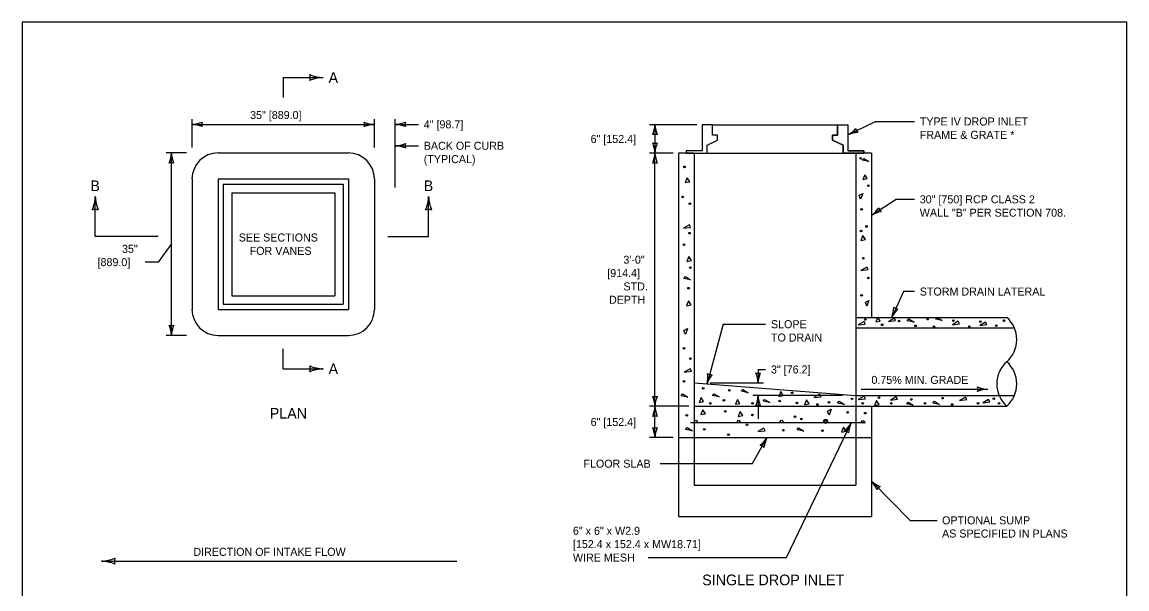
# Model space of a CAD drawing. Extents: x 49991.4 to 50021, y 49987.6 to 50011.4.
# Drawn here: x 50000.34 to 50008.61, y 50007.02 to 50011.26 of the extents above; entities that cross this region are included whole.
import ezdxf

# ---------------------------------------------------------------- set-up
doc = ezdxf.new("R2010")
doc.units = 0
for name, color, linetype in [('Level 1', 7, 'Continuous'), ('Level 2', 7, 'Continuous'), ('Level 3', 7, 'Continuous'), ('Level 4', 7, 'Continuous'), ('Level 6', 7, 'Continuous')]:
    doc.layers.add(name, color=color, linetype=linetype)

msp = doc.modelspace()

# ---------------------------------------------------------------- linework, layer by layer
at = {"layer": 'Level 1'}
for p, q in [((50005.5095, 50010.4937), (50005.4325, 50010.4937)), ((50005.4325, 50010.4937), (50005.4325, 50010.2985)), ((50005.5095, 50010.4937), (50005.4325, 50010.4937)), ((50005.4325, 50010.4937), (50005.4325, 50010.2985)), ((50005.5095, 50010.4169), (50005.5095, 50010.4937)), ((50005.5095, 50010.4169), (50005.5095, 50010.4937)), ((50005.5095, 50010.4937), (50006.4458, 50010.4937)), ((50006.4458, 50010.4169), (50006.4458, 50010.4937)), ((50006.4458, 50010.4937), (50006.5227, 50010.4937)), ((50006.4458, 50010.4937), (50006.4458, 50010.4169)), ((50006.4458, 50010.4937), (50006.5227, 50010.4937)), ((50006.5227, 50010.4937), (50006.5227, 50010.2985)), ((50006.5227, 50010.4937), (50006.5227, 50010.2985)), ((50006.5227, 50010.4937), (50006.5227, 50010.2985)), ((50005.4681, 50010.3404), (50005.5461, 50010.3795)), ((50005.4681, 50010.3404), (50005.5461, 50010.3795)), ((50005.5461, 50010.4169), (50005.5095, 50010.4169)), ((50005.5461, 50010.4169), (50005.5095, 50010.4169)), ((50005.5461, 50010.3795), (50005.5461, 50010.4169)), ((50005.5461, 50010.3795), (50005.5461, 50010.4169)), ((50006.4091, 50010.3795), (50006.4091, 50010.4169)), ((50006.4091, 50010.4169), (50006.4458, 50010.4169)), ((50006.4458, 50010.4169), (50006.4091, 50010.4169)), ((50006.4091, 50010.4169), (50006.4091, 50010.3795)), ((50006.4873, 50010.3404), (50006.4091, 50010.3795)), ((50006.4091, 50010.3795), (50006.4873, 50010.3404)), ((50005.4325, 50010.2985), (50005.3119, 50010.2985)), ((50005.3119, 50010.2985), (50005.3119, 50010.2811)), ((50005.4325, 50010.2985), (50005.3119, 50010.2985)), ((50005.3119, 50010.2985), (50005.3119, 50010.2811)), ((50005.4681, 50010.2811), (50005.4681, 50010.3404)), ((50005.4681, 50010.2811), (50005.4681, 50010.3404)), ((50006.4873, 50010.2811), (50006.4873, 50010.3404)), ((50006.4873, 50010.3404), (50006.4873, 50010.2811)), ((50006.5227, 50010.2985), (50006.6435, 50010.2985)), ((50006.6435, 50010.2985), (50006.5227, 50010.2985)), ((50006.6435, 50010.2985), (50006.6435, 50010.2811)), ((50006.6435, 50010.2811), (50006.6435, 50010.2985)), ((50001.804, 50010.2826), (50002.7806, 50010.2826)), ((50002.7806, 50010.2826), (50002.7806, 50010.2827)), ((50005.3721, 50010.2811), (50005.2551, 50010.2811)), ((50005.2551, 50010.2811), (50005.2551, 50008.1497)), ((50005.3119, 50010.2811), (50005.4681, 50010.2811)), ((50005.3119, 50010.2811), (50005.4681, 50010.2811)), ((50005.3721, 50010.2811), (50005.3721, 50008.3843)), ((50005.4681, 50010.2811), (50006.4873, 50010.2811)), ((50006.6435, 50010.2811), (50006.4873, 50010.2811)), ((50006.4873, 50010.2811), (50006.6435, 50010.2811)), ((50006.7003, 50010.2811), (50006.5831, 50010.2811)), ((50006.5831, 50010.2811), (50006.5831, 50008.3864)), ((50006.7003, 50010.2811), (50006.7003, 50009.0505)), ((50001.6087, 50010.0874), (50001.6087, 50010.0874)), ((50001.6088, 50010.0874), (50001.6088, 50009.1108)), ((50001.804, 50010.0874), (50001.804, 50009.1108)), ((50001.804, 50010.0874), (50002.7806, 50010.0874)), ((50001.843, 50010.0482), (50001.843, 50009.1498)), ((50001.843, 50010.0482), (50002.7416, 50010.0482)), ((50002.7416, 50010.0482), (50002.7416, 50009.1498)), ((50002.7806, 50010.0874), (50002.7806, 50009.1108)), ((50002.9758, 50010.0874), (50002.9758, 50009.1108)), ((50001.9066, 50009.9848), (50001.9066, 50009.2133)), ((50001.9066, 50009.9848), (50002.678, 50009.9848)), ((50002.678, 50009.9848), (50002.678, 50009.2133)), ((50001.843, 50009.1498), (50002.7416, 50009.1498)), ((50001.9066, 50009.2133), (50002.678, 50009.2133)), ((50001.6087, 50009.1108), (50001.6088, 50009.1108)), ((50001.804, 50009.1108), (50002.7806, 50009.1108)), ((50002.9758, 50009.1108), (50002.9759, 50009.1108)), ((50006.5831, 50009.0505), (50007.7142, 50009.0505)), ((50006.5831, 50008.9723), (50007.771, 50008.9723)), ((50001.804, 50008.9155), (50001.804, 50008.9154)), ((50001.804, 50008.9154), (50002.7806, 50008.9154)), ((50005.3721, 50008.5598), (50006.5831, 50008.4646)), ((50006.5831, 50008.4646), (50007.771, 50008.4646)), ((50005.3721, 50008.3843), (50006.5831, 50008.3864)), ((50006.5831, 50008.3864), (50007.7143, 50008.3864)), ((50006.7003, 50008.3864), (50006.7003, 50008.1497)), ((50006.6563, 50008.2606), (50005.3449, 50008.2606)), ((50005.2551, 50008.1497), (50006.7003, 50008.1497))]:
    msp.add_line(p, q, dxfattribs=at)
for points in [[(50008.6146, 50011.2628), (50000.3356, 50011.2628), (50000.3356, 50000.0624), (50008.6146, 50000.0624)], [(50001.6087, 50010.0874), (50001.6087, 50010.0874), (50001.6087, 50010.0874)], [(50001.804, 50008.9155), (50001.804, 50008.9155), (50001.804, 50008.9155)], [(50001.804, 50008.9154), (50001.804, 50008.9154), (50001.804, 50008.9154)], [(50001.804, 50008.9154), (50001.804, 50008.9154), (50001.804, 50008.9154)], [(50002.7806, 50008.9155), (50002.7806, 50008.9155)]]:
    msp.add_lwpolyline(points, close=True, dxfattribs=at)
for points in [[(50006.6427, 50010.2417), (50006.6819, 50010.2177), (50006.6313, 50010.2277), (50006.6427, 50010.2417)], [(50001.6088, 50010.0874), (50001.6088, 50010.0874), (50001.6087, 50010.0874)], [(50005.3197, 50010.0962), (50005.3045, 50010.06), (50005.3383, 50010.0667), (50005.3197, 50010.0962)], [(50006.6499, 50010.1197), (50006.6347, 50010.0835), (50006.6685, 50010.0902), (50006.6499, 50010.1197)], [(50006.6189, 50009.9355), (50006.6077, 50009.9661), (50006.6347, 50009.9795), (50006.6189, 50009.9355)], [(50005.3357, 50009.7431), (50005.2911, 50009.7178), (50005.3449, 50009.7245), (50005.3357, 50009.7431)], [(50006.6365, 50009.6634), (50006.6213, 50009.6272), (50006.6549, 50009.6339), (50006.6365, 50009.6634)], [(50005.3331, 50009.5057), (50005.3181, 50009.4695), (50005.3517, 50009.4762), (50005.3331, 50009.5057)], [(50006.6657, 50009.4277), (50006.6213, 50009.4024), (50006.6751, 50009.4091), (50006.6657, 50009.4277)], [(50005.3057, 50009.356), (50005.3449, 50009.3319), (50005.2945, 50009.342), (50005.3057, 50009.356)], [(50005.3299, 50009.1736), (50005.3147, 50009.1373), (50005.3483, 50009.1441), (50005.3299, 50009.1736)], [(50006.6661, 50009.1336), (50006.6549, 50009.1642), (50006.6819, 50009.1776), (50006.6661, 50009.1336)], [(50006.7479, 50009.0524), (50006.7329, 50009.0162), (50006.7665, 50009.0229), (50006.7479, 50009.0524)], [(50006.6446, 50009.0196), (50006.6002, 50008.9943), (50006.654, 50009.001), (50006.6446, 50009.0196)], [(50006.8721, 50009.045), (50006.8277, 50009.0197), (50006.8815, 50009.0264), (50006.8721, 50009.045)], [(50006.9801, 50009.0389), (50007.0193, 50009.0148), (50006.9689, 50009.0249), (50006.9801, 50009.0389)], [(50007.1922, 50009.0503), (50007.2314, 50009.0262), (50007.181, 50009.0363), (50007.1922, 50009.0503)], [(50007.351, 50009.0212), (50007.3066, 50008.9959), (50007.3604, 50009.0026), (50007.351, 50009.0212)], [(50007.5561, 50009.0149), (50007.5117, 50008.9896), (50007.5655, 50008.9963), (50007.5561, 50009.0149)], [(50005.3057, 50008.9223), (50005.2945, 50008.9528), (50005.3215, 50008.9663), (50005.3057, 50008.9223)], [(50005.3423, 50008.6661), (50005.2979, 50008.6408), (50005.3517, 50008.6475), (50005.3423, 50008.6661)], [(50005.2855, 50008.477), (50005.3247, 50008.4529), (50005.2743, 50008.463), (50005.2855, 50008.477)], [(50005.5189, 50008.479), (50005.5581, 50008.4549), (50005.5077, 50008.465), (50005.5189, 50008.479)], [(50005.7368, 50008.5107), (50005.776, 50008.4866), (50005.7256, 50008.4967), (50005.7368, 50008.5107)], [(50006.0208, 50008.4953), (50006.0056, 50008.459), (50006.0392, 50008.4657), (50006.0208, 50008.4953)], [(50006.3131, 50008.4751), (50006.2685, 50008.4498), (50006.3223, 50008.4565), (50006.3131, 50008.4751)], [(50005.4232, 50008.4497), (50005.4082, 50008.4135), (50005.4418, 50008.4202), (50005.4232, 50008.4497)], [(50005.6956, 50008.4355), (50005.6806, 50008.3993), (50005.7142, 50008.406), (50005.6956, 50008.4355)], [(50005.8991, 50008.4362), (50005.9383, 50008.4121), (50005.8879, 50008.4222), (50005.8991, 50008.4362)], [(50006.2146, 50008.4326), (50006.1996, 50008.3964), (50006.2332, 50008.4031), (50006.2146, 50008.4326)], [(50006.4582, 50008.422), (50006.4974, 50008.3979), (50006.447, 50008.408), (50006.4582, 50008.422)], [(50006.6462, 50008.4602), (50006.6018, 50008.4349), (50006.6556, 50008.4416), (50006.6462, 50008.4602)], [(50006.7393, 50008.4269), (50006.7243, 50008.3907), (50006.7579, 50008.3974), (50006.7393, 50008.4269)], [(50006.8864, 50008.4555), (50006.842, 50008.4302), (50006.8958, 50008.4369), (50006.8864, 50008.4555)], [(50006.9743, 50008.4162), (50007.0135, 50008.3921), (50006.9631, 50008.4022), (50006.9743, 50008.4162)], [(50007.1722, 50008.422), (50007.2114, 50008.3979), (50007.161, 50008.408), (50007.1722, 50008.422)], [(50007.4051, 50008.4539), (50007.3607, 50008.4286), (50007.4145, 50008.4353), (50007.4051, 50008.4539)], [(50007.5785, 50008.4364), (50007.5341, 50008.4111), (50007.5879, 50008.4178), (50007.5785, 50008.4364)], [(50005.4375, 50008.3583), (50005.4225, 50008.3221), (50005.4561, 50008.3288), (50005.4375, 50008.3583)], [(50005.7171, 50008.3449), (50005.7019, 50008.3087), (50005.7357, 50008.3153), (50005.7171, 50008.3449)], [(50006.3833, 50008.3183), (50006.3721, 50008.3489), (50006.3991, 50008.3623), (50006.3833, 50008.3183)], [(50005.3191, 50008.2253), (50005.3585, 50008.2013), (50005.3079, 50008.2113), (50005.3191, 50008.2253)], [(50006.4917, 50008.2275), (50006.4765, 50008.1912), (50006.5101, 50008.1979), (50006.4917, 50008.2275)], [(50005.8947, 50008.2199), (50005.8501, 50008.1946), (50005.9039, 50008.2013), (50005.8947, 50008.2199)], [(50006.1543, 50008.222), (50006.1935, 50008.1979), (50006.1431, 50008.208), (50006.1543, 50008.222)]]:
    msp.add_lwpolyline(points, dxfattribs=at)
for centre, radius in [((50006.6196, 50010.242), 0.00606), ((50005.2995, 50010.1783), 0.00606), ((50006.6768, 50010.0373), 0.00606), ((50005.2861, 50009.9535), 0.00606), ((50005.3399, 50009.9031), 0.00606), ((50006.6263, 50009.8595), 0.00606), ((50006.6634, 50009.732), 0.00606), ((50005.3366, 50009.6817), 0.00606), ((50006.6229, 50009.6985), 0.00606), ((50005.2962, 50009.5945), 0.00606), ((50006.6398, 50009.4938), 0.00606), ((50005.3433, 50009.4234), 0.00606), ((50006.6768, 50009.3462), 0.00606), ((50005.3298, 50009.269), 0.00606), ((50006.6263, 50009.2154), 0.00606), ((50006.6549, 50009.0348), 0.00606), ((50006.7806, 50008.9952), 0.00606), ((50006.9072, 50009.0234), 0.00606), ((50007.0304, 50008.9873), 0.00606), ((50007.1222, 50009.0377), 0.00606), ((50007.1688, 50008.9809), 0.00606), ((50007.3143, 50009.0262), 0.00606), ((50007.4344, 50008.981), 0.00606), ((50007.5156, 50009.019), 0.00606), ((50007.6365, 50008.9889), 0.00606), ((50007.6937, 50009.0253), 0.00606), ((50005.2962, 50008.8195), 0.00606), ((50005.3433, 50008.7423), 0.00606), ((50005.2962, 50008.5712), 0.00606), ((50005.4395, 50008.5189), 0.00606), ((50005.6351, 50008.5046), 0.00606), ((50006.1066, 50008.4854), 0.00606), ((50005.4936, 50008.4064), 0.00606), ((50005.594, 50008.4293), 0.00606), ((50005.809, 50008.4064), 0.00606), ((50006.0126, 50008.4236), 0.00606), ((50006.1416, 50008.4093), 0.00606), ((50006.2965, 50008.3979), 0.00606), ((50006.3825, 50008.415), 0.00606), ((50006.5544, 50008.4404), 0.00606), ((50006.6348, 50008.4064), 0.00606), ((50006.7567, 50008.4485), 0.00606), ((50006.8498, 50008.4064), 0.00606), ((50006.9985, 50008.4358), 0.00606), ((50007.1021, 50008.4064), 0.00606), ((50007.234, 50008.4453), 0.00606), ((50007.3057, 50008.3979), 0.00606), ((50007.4997, 50008.4073), 0.00606), ((50007.6174, 50008.4421), 0.00606), ((50007.6556, 50008.4073), 0.00606), ((50005.3164, 50008.3162), 0.00606), ((50005.606, 50008.3464), 0.00606), ((50005.808, 50008.3196), 0.00606), ((50006.1279, 50008.3061), 0.00606), ((50006.5219, 50008.3397), 0.00606), ((50006.6533, 50008.333), 0.00606), ((50005.3845, 50008.2705), 0.00994), ((50005.7053, 50008.2705), 0.00994), ((50005.7676, 50008.2457), 0.00606), ((50006.0261, 50008.2705), 0.00994), ((50006.1751, 50008.2894), 0.00606), ((50006.357, 50008.272), 0.0147), ((50006.3584, 50008.272), 0.00994), ((50006.6361, 50008.2691), 0.00994), ((50005.4477, 50008.2122), 0.00606), ((50005.6295, 50008.1719), 0.00606), ((50006.0404, 50008.2055), 0.00606), ((50006.3333, 50008.2021), 0.00606)]:
    msp.add_circle(centre, radius, dxfattribs=at)
for centre, radius, start, end in [((50001.804, 50010.0873), 0.1953, 90.00436, 179.96698), ((50002.7805, 50010.0874), 0.1953, 360, 89.96698), ((50001.804, 50009.1108), 0.1953, 180, 269.99565), ((50002.7806, 50009.1107), 0.1953, 270, 0.02574), ((50007.5676, 50008.8844), 0.2215, 311.46351, 48.55861), ((50007.861, 50008.5524), 0.2215, 131.46351, 228.53649), ((50007.5676, 50008.5524), 0.2215, 311.46351, 48.53649)]:
    msp.add_arc(centre, radius, start, end, dxfattribs=at)
at = {"layer": 'Level 3'}
for p, q in [((50001.6088, 50010.3226), (50001.6088, 50010.5368)), ((50001.6088, 50010.4968), (50002.9758, 50010.4968)), ((50002.9758, 50010.3226), (50002.9758, 50010.5368)), ((50003.1322, 50010.0242), (50003.1322, 50010.5368)), ((50003.1322, 50010.4968), (50003.3056, 50010.4968)), ((50005.3925, 50010.4937), (50005.0383, 50010.4937)), ((50005.0783, 50010.4937), (50005.0783, 50010.2811)), ((50006.5227, 50010.4174), (50006.7297, 50010.5182)), ((50006.7297, 50010.5182), (50007.0224, 50010.5182)), ((50003.1322, 50010.3364), (50003.3056, 50010.3364)), ((50001.5688, 50010.2826), (50001.4142, 50010.2826)), ((50001.4542, 50008.9154), (50001.4542, 50010.2826)), ((50005.2151, 50010.2811), (50005.0383, 50010.2811)), ((50005.0783, 50008.3843), (50005.0783, 50010.2811)), ((50006.7003, 50009.8153), (50006.8856, 50009.9351)), ((50006.8856, 50009.9351), (50007.0224, 50009.9351)), ((50001.3589, 50009.4644), (50001.4542, 50009.599)), ((50001.3589, 50009.4644), (50001.2589, 50009.4644)), ((50006.9397, 50009.2442), (50006.8522, 50009.0505)), ((50007.0224, 50009.2442), (50006.9397, 50009.2442)), ((50005.5897, 50008.9996), (50005.4683, 50008.5522)), ((50005.5897, 50008.9996), (50005.9074, 50008.9996)), ((50001.5687, 50008.9154), (50001.4142, 50008.9154)), ((50005.8507, 50008.6603), (50005.8507, 50008.5598)), ((50005.8507, 50008.6603), (50005.9074, 50008.6603)), ((50005.4921, 50008.5598), (50005.8907, 50008.5598)), ((50006.6231, 50008.5123), (50007.5716, 50008.5123)), ((50006.4831, 50008.4646), (50005.8107, 50008.4646)), ((50005.8507, 50008.4646), (50005.8507, 50008.2912)), ((50005.3321, 50008.3843), (50005.0383, 50008.3843)), ((50005.0783, 50008.1497), (50005.0783, 50008.3843)), ((50006.0641, 50007.2517), (50006.5479, 50008.2606)), ((50005.2151, 50008.1497), (50005.0383, 50008.1497)), ((50005.8056, 50007.9543), (50005.9182, 50008.1497)), ((50005.8056, 50007.9543), (50005.1161, 50007.9547)), ((50006.7003, 50007.8247), (50006.99, 50007.5284)), ((50006.99, 50007.5284), (50007.1919, 50007.5284)), ((50005.028, 50007.2517), (50006.0641, 50007.2517)), ((50000.9296, 50007.2242), (50003.5928, 50007.2242))]:
    msp.add_line(p, q, dxfattribs=at)
for centre, radius, start, end in [((50002.4213, 50010.8468), 0.073, 342.13882, 17.86118), ((50002.6075, 50011.1571), 0.3107, 247.92284, 267.17269), ((50002.6044, 50010.5506), 0.2964, 92.36048, 112.54399), ((50001.5973, 50010.7295), 0.233, 272.82731, 292.07716), ((50001.5973, 50010.7295), 0.233, 272.82731, 292.07716), ((50001.5996, 50010.2747), 0.2223, 67.45601, 87.63952), ((50001.5996, 50010.2747), 0.2223, 67.45601, 87.63952), ((50001.737, 50010.4968), 0.0548, 162.13882, 197.86118), ((50001.737, 50010.4968), 0.0548, 162.13882, 197.86118), ((50002.985, 50010.7189), 0.2223, 247.45601, 267.63952), ((50002.8476, 50010.4968), 0.0548, 342.13882, 17.86118), ((50002.9873, 50010.2641), 0.233, 92.82731, 112.07716), ((50003.1207, 50010.7295), 0.233, 272.82731, 292.07716), ((50003.123, 50010.2747), 0.2223, 67.45601, 87.63952), ((50003.2604, 50010.4968), 0.0548, 162.13882, 197.86118), ((50004.8562, 50010.5029), 0.2223, 337.45601, 357.63952), ((50005.311, 50010.5052), 0.233, 182.82731, 202.07716), ((50006.4105, 50010.6216), 0.233, 298.79138, 318.04123), ((50006.638, 50010.4735), 0.0548, 188.10289, 223.82525), ((50005.0783, 50010.3655), 0.0548, 72.13882, 107.86118), ((50006.6117, 50010.2137), 0.2223, 93.42008, 113.60359), ((50003.1207, 50010.5691), 0.233, 272.82731, 292.07716), ((50003.123, 50010.1143), 0.2223, 67.45601, 87.63952), ((50003.2604, 50010.3364), 0.0548, 162.13882, 197.86118), ((50005.0783, 50010.4093), 0.0548, 252.13882, 287.86118), ((50004.8456, 50010.2696), 0.233, 2.82731, 22.07716), ((50005.3004, 50010.2719), 0.2223, 157.45601, 177.63952), ((50001.2321, 50010.2918), 0.2223, 337.45601, 357.63952), ((50001.6869, 50010.2941), 0.233, 182.82731, 202.07716), ((50004.8562, 50010.2903), 0.2223, 337.45601, 357.63952), ((50005.311, 50010.2926), 0.233, 182.82731, 202.07716), ((50001.4542, 50010.1544), 0.0548, 72.13882, 107.86118), ((50005.0783, 50010.1529), 0.0548, 72.13882, 107.86118), ((50000.574, 50009.9719), 0.3107, 337.92284, 357.17269), ((50001.1805, 50009.9688), 0.2964, 182.36048, 202.54399), ((50003.0859, 50009.9688), 0.2964, 337.45601, 357.63952), ((50003.6924, 50009.9719), 0.3107, 182.82731, 202.07716), ((50000.8843, 50009.7856), 0.073, 72.13882, 107.86118), ((50003.3821, 50009.7856), 0.073, 72.13882, 107.86118), ((50006.5643, 50010.0045), 0.233, 305.71075, 324.9606), ((50006.8132, 50009.6238), 0.2223, 100.33945, 120.52296), ((50006.808, 50009.8849), 0.0548, 195.02226, 230.74462), ((50006.6354, 50009.1358), 0.233, 338.51721, 357.76706), ((50007.0509, 50008.9507), 0.2223, 133.14591, 153.32942), ((50006.905, 50009.1673), 0.0548, 227.82872, 263.55108), ((50001.4542, 50009.0436), 0.0548, 252.13882, 287.86118), ((50001.2215, 50008.9039), 0.233, 2.82731, 22.07716), ((50001.4542, 50009.0436), 0.0548, 252.13882, 287.86118), ((50001.2215, 50008.9039), 0.233, 2.82731, 22.07716), ((50001.6763, 50008.9062), 0.2223, 157.45601, 177.63952), ((50001.6763, 50008.9062), 0.2223, 157.45601, 177.63952), ((50002.6044, 50008.9616), 0.2964, 247.45601, 267.63952), ((50002.4212, 50008.6654), 0.073, 342.13882, 17.86118), ((50002.6075, 50008.3551), 0.3107, 92.82731, 112.07716), ((50005.2407, 50008.6021), 0.233, 347.64757, 6.89742), ((50005.6803, 50008.4852), 0.2223, 142.27627, 162.45978), ((50005.5019, 50008.676), 0.0548, 236.95908, 272.68144), ((50005.8507, 50008.688), 0.0548, 252.13882, 287.86118), ((50005.618, 50008.5483), 0.233, 2.82731, 22.07716), ((50005.8507, 50008.688), 0.0548, 252.13882, 287.86118), ((50005.618, 50008.5483), 0.233, 2.82731, 22.07716), ((50006.0728, 50008.5506), 0.2223, 157.45601, 177.63952), ((50006.0728, 50008.5506), 0.2223, 157.45601, 177.63952), ((50007.5808, 50008.7344), 0.2223, 247.45601, 267.63952), ((50007.4434, 50008.5123), 0.0548, 342.13882, 17.86118), ((50007.5831, 50008.2796), 0.233, 92.82731, 112.07716), ((50005.0783, 50008.5125), 0.0548, 252.13882, 287.86118), ((50004.8456, 50008.3728), 0.233, 2.82731, 22.07716), ((50005.3004, 50008.3751), 0.2223, 157.45601, 177.63952), ((50005.6286, 50008.4738), 0.2223, 337.45601, 357.63952), ((50005.8507, 50008.3364), 0.0548, 72.13882, 107.86118), ((50006.0834, 50008.4761), 0.233, 182.82731, 202.07716), ((50004.8562, 50008.3935), 0.2223, 337.45601, 357.63952), ((50005.0783, 50008.2561), 0.0548, 72.13882, 107.86118), ((50005.311, 50008.3958), 0.233, 182.82731, 202.07716), ((50005.0783, 50008.2779), 0.0548, 252.13882, 287.86118), ((50004.8456, 50008.1382), 0.233, 2.82731, 22.07716), ((50005.3004, 50008.1405), 0.2223, 157.45601, 177.63952), ((50006.3546, 50008.3703), 0.2223, 310.2596, 330.44311), ((50006.7602, 50008.1645), 0.233, 155.6309, 174.88075), ((50005.7303, 50008.2685), 0.2223, 307.50315, 327.68666), ((50006.1256, 50008.0435), 0.233, 152.87445, 172.1243), ((50006.4893, 50008.1466), 0.0548, 44.94241, 80.66477), ((50005.8542, 50008.0386), 0.0548, 42.18596, 77.90832), ((50006.537, 50007.6738), 0.2223, 22.55713, 42.74064), ((50006.8564, 50007.9977), 0.233, 227.92843, 247.17828), ((50006.7911, 50007.7342), 0.0548, 117.23994, 152.9623), ((50000.9143, 50007.5345), 0.3107, 272.82731, 292.07716), ((50001.1006, 50007.2242), 0.073, 162.13882, 197.86118), ((50000.9174, 50006.928), 0.2964, 67.45601, 87.63952)]:
    msp.add_arc(centre, radius, start, end, dxfattribs=at)
at = {"layer": 'Level 4'}
for p, q in [((50005.3721, 50008.3843), (50005.3721, 50007.7946)), ((50006.5831, 50008.3864), (50006.5831, 50007.7946)), ((50005.2551, 50008.1497), (50005.2551, 50007.56)), ((50006.7003, 50008.1497), (50006.7003, 50007.56)), ((50005.3721, 50007.7946), (50006.5831, 50007.7946)), ((50005.2551, 50007.56), (50006.7003, 50007.56))]:
    msp.add_line(p, q, dxfattribs=at)
at = {"layer": 'Level 6'}
for p, q in [((50002.2922, 50010.8468), (50002.2922, 50010.6968)), ((50002.2922, 50010.8468), (50002.5922, 50010.8468)), ((50000.8843, 50009.6566), (50000.8843, 50009.9566)), ((50003.3821, 50009.6566), (50003.3821, 50009.9566)), ((50001.3542, 50009.6566), (50000.8843, 50009.6566)), ((50003.0758, 50009.6566), (50003.3821, 50009.6566)), ((50002.2922, 50008.6654), (50002.2922, 50008.8154)), ((50002.2922, 50008.6654), (50002.5922, 50008.6654))]:
    msp.add_line(p, q, dxfattribs=at)

# ---------------------------------------------------------------- texts
at = {"layer": 'Level 2'}
for s, height, p in [('A', 0.08, (50002.6322, 50010.8068)), ('35" [889.0]', 0.06, (50002.0442, 50010.5368)), ('TYPE IV DROP INLET', 0.06, (50007.0624, 50010.4882)), ('4" [98.7]', 0.06, (50003.3456, 50010.4668)), ('6" [152.4]', 0.06, (50004.5958, 50010.3574)), ('FRAME & GRATE *', 0.06, (50007.0624, 50010.3882)), ('BACK OF CURB', 0.06, (50003.3456, 50010.3064)), ('(TYPICAL)', 0.06, (50003.3456, 50010.2064)), ('B', 0.08, (50000.8473, 50009.9966)), ('B', 0.08, (50003.3451, 50009.9966)), ('30" [750] RCP CLASS 2', 0.06, (50007.0624, 50009.9051)), ('WALL "B" PER SECTION 708.', 0.06, (50007.0624, 50009.8051)), ('SEE SECTIONS', 0.06, (50001.9592, 50009.619)), ('35"', 0.06, (50001.0844, 50009.5344)), ('FOR VANES', 0.06, (50002.0409, 50009.519)), ('[889.0]', 0.06, (50000.901, 50009.4344)), ('3\'-0"', 0.06, (50004.8414, 50009.4527)), ('[914.4]', 0.06, (50004.7204, 50009.3527)), ('STD.', 0.06, (50004.842, 50009.2527)), ('STORM DRAIN LATERAL', 0.06, (50007.0624, 50009.2142)), ('DEPTH', 0.06, (50004.7338, 50009.1527)), ('SLOPE', 0.06, (50005.9474, 50008.9696)), ('TO DRAIN', 0.06, (50005.9474, 50008.8696)), ('A', 0.08, (50002.6322, 50008.6254)), ('3" [76.2]', 0.06, (50005.9474, 50008.6303)), ('0.75% MIN. GRADE', 0.06, (50006.7001, 50008.5523)), ('PLAN', 0.08, (50002.1915, 50008.2918)), ('6" [152.4]', 0.06, (50004.5958, 50008.237)), ('FLOOR SLAB', 0.06, (50004.542, 50007.9247)), ('OPTIONAL SUMP ', 0.06, (50007.2295, 50007.5002)), ('6" x 6" x W2.9', 0.06, (50004.4633, 50007.4217)), ('AS SPECIFIED IN PLANS', 0.06, (50007.2295, 50007.4013)), ('DIRECTION OF INTAKE FLOW', 0.06, (50001.619, 50007.2642)), ('[152.4 x 152.4 x MW18.71]', 0.06, (50004.4633, 50007.3217)), ('WIRE MESH', 0.06, (50004.4633, 50007.2217)), ('SINGLE DROP INLET', 0.08, (50005.4322, 50007.0438))]:
    msp.add_text(s, height=height, dxfattribs=at).set_placement(p)

doc.saveas('drawing.dxf')
